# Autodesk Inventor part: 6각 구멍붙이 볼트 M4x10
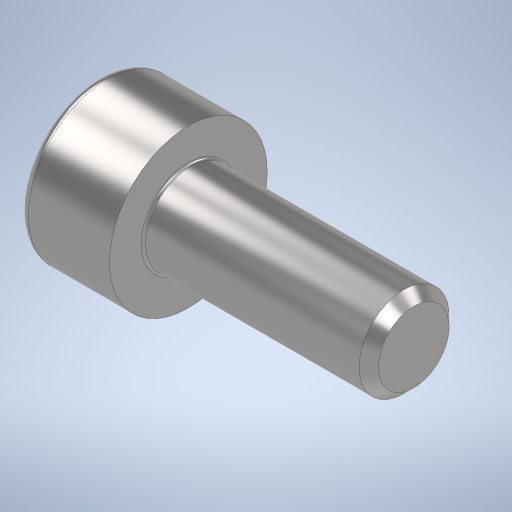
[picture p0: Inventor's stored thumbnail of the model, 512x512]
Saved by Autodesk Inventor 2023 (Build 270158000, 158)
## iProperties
Created: 2025-10
Part Number: 6각 구멍붙이 볼트 M4x10
Material: 강철, 연강
Description: 6각머리 태핑 나사
Document SubType Name: Modeling
Designer: home
Density: 7.85 g/cm^3
Appearance: 기본값
Author: jhkim
Sending System: Autodesk Inventor 2026
Preprocessor: ST-DEVELOPER v20.1
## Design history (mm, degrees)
sketch "스케치1"
  geometry: 1 further point
  constraints: 1 other
feature "Solid1"
node "솔리드1"
